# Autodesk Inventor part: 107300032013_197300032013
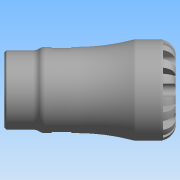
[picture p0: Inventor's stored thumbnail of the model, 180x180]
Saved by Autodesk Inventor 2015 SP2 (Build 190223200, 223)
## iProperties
Created: 2016-12
Part Number: 107300032013_197300032013
Material: Generic
Description: PLASSON FEMALE INTEGRAL BRASS THREAD 32X1.1/4" SERIES 1
Document SubType Name: Modeling
Designer: KIM
Density: 1 g/cm^3
Appearance: Default
Author: KIM
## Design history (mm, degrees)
derived "1073.ipt"
feature "Solid1::1073.ipt"
tag "TaggingFeature1"
body "Solid1"
other parameters: "d0" = 98, "d1" = 23.52, "d2" = 32, "d4" = 58, "d6" = 56, "d8" = 49.3, "d13" = 7.2, "d14" = 7.2, "d15" = 0, "d17" = 360 deg, "d19" = 8 deg, "d20" = 0.64, "d21" = 0.64, "d22" = 8 deg, "d24" = 0, "d26" = 360 deg, "d32" = 5.8, "d33" = 5.8, "d39" = 1.16856, "d42" = 38.952, "d43" = 45.24, "d46" = 2.66667, "d47" = 21, "d48" = 37.0044, "d50" = 6.93, "d51" = 0.58, "d54" = 11.2, "d55" = 7.04, "d57" = 14.112, "d58" = 0, "d68" = 360 deg, "d72" = 0.64, "d74" = 0, "d76" = 9.52, "d_" = 32, "E_" = 58, "H_" = 98, "l_" = 56, "G_" = 38.952, "l_2" = 21, "d9" = 9, "d11" = 58, "d49" = 21
